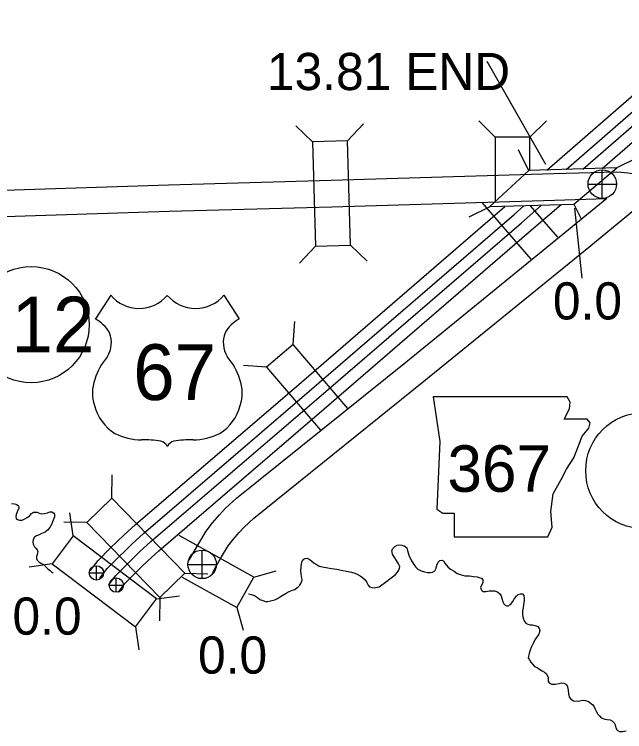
# Model space of a CAD drawing. Extents: x -939622 to -934222, y 1383701 to 1385301.
# Drawn here: x -936430.88 to -936410.08, y 1384424.88 to 1384449.32 of the extents above; entities that cross this region are included whole.
import ezdxf

# ---------------------------------------------------------------- set-up
doc = ezdxf.new("R2010")
doc.units = 0
for name, color, linetype in [('10', 7, 'Continuous'), ('15', 7, 'Continuous'), ('2', 7, 'Continuous'), ('20', 7, 'Continuous'), ('21', 7, 'Continuous'), ('22', 7, 'Continuous'), ('25', 7, 'Continuous'), ('26', 7, 'Continuous'), ('27', 7, 'Continuous')]:
    doc.layers.add(name, color=color, linetype=linetype)

msp = doc.modelspace()

# ---------------------------------------------------------------- linework, layer by layer
at = {"layer": '10'}
for points in [[(-936424.918, 1384430.721), (-936424.781, 1384430.966), (-936424.592, 1384431.291), (-936424.339, 1384431.72), (-936424.127, 1384431.995), (-936423.89, 1384432.276), (-936423.681, 1384432.493), (-936423.305, 1384432.841), (-936417.485, 1384437.522), (-936411.993, 1384441.99), (-936410.688, 1384443.056)], [(-936424.132, 1384430.282), (-936423.999, 1384430.52), (-936423.815, 1384430.836), (-936423.592, 1384431.215), (-936423.426, 1384431.43), (-936423.221, 1384431.673), (-936423.05, 1384431.851), (-936422.717, 1384432.159), (-936416.919, 1384436.823), (-936411.424, 1384441.292), (-936409.432, 1384442.92)]]:
    msp.add_lwpolyline(points, dxfattribs=at)
at = {"layer": '15'}
for points in [[(-936412.735, 1384444.016), (-936406.627, 1384449.323)], [(-936412.076, 1384444.042), (-936406.36, 1384449.008)], [(-936411.501, 1384444.045), (-936406.118, 1384448.722)], [(-936410.842, 1384444.071), (-936405.851, 1384448.408)], [(-936431.586, 1384443.322), (-936425.629, 1384443.512), (-936420.085, 1384443.668), (-936412.497, 1384443.896), (-936410.371, 1384443.959), (-936410.2, 1384443.942), (-936409.976, 1384443.925), (-936409.737, 1384443.884), (-936409.702, 1384443.877)], [(-936431.567, 1384442.422), (-936425.602, 1384442.613), (-936420.058, 1384442.769), (-936412.47, 1384442.997), (-936410.703, 1384443.048)], [(-936427.665, 1384429.89), (-936427.432, 1384430.198), (-936427.055, 1384430.572), (-936426.822, 1384430.803), (-936426.612, 1384431.007), (-936426.226, 1384431.357), (-936420.585, 1384436.197), (-936413.599, 1384442.222), (-936412.914, 1384442.817)], [(-936427.335, 1384429.641), (-936427.12, 1384429.926), (-936426.765, 1384430.279), (-936426.534, 1384430.508), (-936426.329, 1384430.706), (-936425.953, 1384431.047), (-936420.316, 1384435.885), (-936413.329, 1384441.91), (-936412.249, 1384442.849)], [(-936428.293, 1384430.364), (-936428.027, 1384430.717), (-936427.61, 1384431.131), (-936427.374, 1384431.365), (-936427.15, 1384431.582), (-936426.747, 1384431.947), (-936421.099, 1384436.794), (-936414.16, 1384442.778)], [(-936427.964, 1384430.115), (-936427.715, 1384430.445), (-936427.32, 1384430.838), (-936427.085, 1384431.071), (-936426.868, 1384431.281), (-936426.474, 1384431.638), (-936420.83, 1384436.482), (-936413.844, 1384442.505), (-936413.512, 1384442.794)]]:
    msp.add_lwpolyline(points, dxfattribs=at)
at = {"layer": '2'}
for points in [[(-936430.972, 1384432.656), (-936430.875, 1384432.644), (-936430.827, 1384432.63), (-936430.784, 1384432.607), (-936430.742, 1384432.575), (-936430.722, 1384432.531), (-936430.724, 1384432.491), (-936430.77, 1384432.403), (-936430.799, 1384432.342), (-936430.815, 1384432.285), (-936430.825, 1384432.2), (-936430.814, 1384432.143), (-936430.775, 1384432.108), (-936430.708, 1384432.089), (-936430.618, 1384432.094), (-936430.526, 1384432.13), (-936430.426, 1384432.187), (-936430.355, 1384432.249), (-936430.294, 1384432.322), (-936430.232, 1384432.357), (-936430.169, 1384432.365), (-936430.1, 1384432.361), (-936430.03, 1384432.329), (-936429.943, 1384432.308), (-936429.85, 1384432.319), (-936429.746, 1384432.34), (-936429.666, 1384432.369), (-936429.597, 1384432.371), (-936429.551, 1384432.339), (-936429.514, 1384432.289), (-936429.517, 1384432.199), (-936429.585, 1384432.034), (-936429.616, 1384431.946), (-936429.673, 1384431.839), (-936429.746, 1384431.747), (-936429.831, 1384431.679), (-936429.938, 1384431.631), (-936430.035, 1384431.586), (-936430.124, 1384431.551), (-936430.192, 1384431.51)], [(-936430.192, 1384431.51), (-936430.241, 1384431.436), (-936430.254, 1384431.349), (-936430.237, 1384431.268), (-936430.19, 1384431.185), (-936430.144, 1384431.135), (-936430.097, 1384431.076), (-936430.084, 1384431.013), (-936430.102, 1384430.92), (-936430.121, 1384430.847), (-936430.12, 1384430.784), (-936430.1, 1384430.727), (-936430.048, 1384430.674), (-936429.975, 1384430.622), (-936429.886, 1384430.576), (-936429.813, 1384430.512), (-936429.742, 1384430.433), (-936429.665, 1384430.369), (-936429.589, 1384430.31), (-936429.554, 1384430.301)], [(-936422.508, 1384429.391), (-936422.411, 1384429.348), (-936422.323, 1384429.321), (-936422.236, 1384429.323), (-936422.099, 1384429.351), (-936422.001, 1384429.38), (-936421.909, 1384429.422), (-936421.838, 1384429.469), (-936421.753, 1384429.528), (-936421.617, 1384429.607), (-936421.519, 1384429.664), (-936421.4, 1384429.7), (-936421.323, 1384429.732), (-936421.253, 1384429.788), (-936421.2, 1384429.829), (-936421.153, 1384429.878), (-936421.121, 1384429.927), (-936421.093, 1384429.985), (-936421.076, 1384430.049), (-936421.1, 1384430.249), (-936421.112, 1384430.375), (-936421.106, 1384430.505), (-936421.091, 1384430.599), (-936421.066, 1384430.69), (-936421.017, 1384430.76), (-936420.967, 1384430.788), (-936420.904, 1384430.79), (-936420.803, 1384430.739), (-936420.736, 1384430.692), (-936420.659, 1384430.628), (-936420.562, 1384430.571), (-936420.486, 1384430.527), (-936420.377, 1384430.497), (-936420.196, 1384430.463), (-936420.07, 1384430.442), (-936419.886, 1384430.417), (-936419.684, 1384430.38), (-936419.558, 1384430.353), (-936419.395, 1384430.316), (-936419.274, 1384430.28), (-936419.192, 1384430.252), (-936419.092, 1384430.191), (-936419.009, 1384430.139), (-936418.929, 1384430.057), (-936418.87, 1384429.963), (-936418.817, 1384429.871), (-936418.776, 1384429.818), (-936418.697, 1384429.79), (-936418.619, 1384429.786), (-936418.446, 1384429.823), (-936418.184, 1384430.014), (-936418.04, 1384430.123), (-936417.902, 1384430.232), (-936417.817, 1384430.318), (-936417.78, 1384430.382), (-936417.749, 1384430.459), (-936417.747, 1384430.516), (-936417.783, 1384430.599), (-936417.854, 1384430.711), (-936417.917, 1384430.806), (-936417.961, 1384430.874), (-936417.989, 1384430.936), (-936418.009, 1384430.996), (-936418.01, 1384431.059), (-936417.973, 1384431.135), (-936417.912, 1384431.191), (-936417.832, 1384431.232), (-936417.763, 1384431.249), (-936417.676, 1384431.24), (-936417.594, 1384431.212), (-936417.509, 1384431.142), (-936417.479, 1384431.058), (-936417.433, 1384430.894), (-936417.36, 1384430.725), (-936417.26, 1384430.574), (-936417.195, 1384430.485), (-936417.124, 1384430.421), (-936417.012, 1384430.367), (-936416.9, 1384430.328), (-936416.797, 1384430.306), (-936416.692, 1384430.303), (-936416.624, 1384430.32), (-936416.553, 1384430.367), (-936416.501, 1384430.455), (-936416.483, 1384430.552), (-936416.44, 1384430.653), (-936416.379, 1384430.711), (-936416.313, 1384430.731), (-936416.259, 1384430.706), (-936416.203, 1384430.626), (-936416.109, 1384430.496), (-936416.015, 1384430.423), (-936415.89, 1384430.348), (-936415.789, 1384430.276), (-936415.689, 1384430.236), (-936415.526, 1384430.198), (-936415.373, 1384430.188), (-936415.228, 1384430.173), (-936415.102, 1384430.153), (-936415.033, 1384430.139), (-936414.954, 1384430.111)], [(-936414.954, 1384430.111), (-936414.913, 1384430.055), (-936414.911, 1384429.965), (-936414.991, 1384429.798), (-936414.961, 1384429.708), (-936414.909, 1384429.664), (-936414.813, 1384429.655), (-936414.694, 1384429.685), (-936414.583, 1384429.685), (-936414.514, 1384429.678), (-936414.414, 1384429.653), (-936414.337, 1384429.583), (-936414.293, 1384429.506), (-936414.257, 1384429.384), (-936414.228, 1384429.306), (-936414.2, 1384429.244), (-936414.157, 1384429.194), (-936414.108, 1384429.165), (-936414.054, 1384429.167), (-936413.971, 1384429.214), (-936413.893, 1384429.315), (-936413.832, 1384429.419), (-936413.771, 1384429.499), (-936413.713, 1384429.552), (-936413.633, 1384429.581), (-936413.564, 1384429.583), (-936413.514, 1384429.518), (-936413.503, 1384429.431), (-936413.506, 1384429.337), (-936413.53, 1384429.216), (-936413.542, 1384429.108), (-936413.564, 1384428.996), (-936413.563, 1384428.87), (-936413.542, 1384428.747), (-936413.504, 1384428.655), (-936413.445, 1384428.581), (-936413.381, 1384428.541), (-936413.296, 1384428.522), (-936413.224, 1384428.518), (-936413.125, 1384428.502), (-936413.04, 1384428.471), (-936412.99, 1384428.397), (-936412.976, 1384428.317), (-936413.003, 1384428.202), (-936413.143, 1384428.017), (-936413.188, 1384427.908), (-936413.262, 1384427.756), (-936413.298, 1384427.658), (-936413.337, 1384427.546), (-936413.359, 1384427.455), (-936413.364, 1384427.398), (-936413.32, 1384427.327), (-936413.276, 1384427.256), (-936413.217, 1384427.188), (-936413.149, 1384427.103), (-936413.067, 1384427.066), (-936413, 1384427.025), (-936412.887, 1384426.959), (-936412.808, 1384426.913), (-936412.756, 1384426.866), (-936412.712, 1384426.789), (-936412.692, 1384426.724), (-936412.691, 1384426.655), (-936412.683, 1384426.595), (-936412.639, 1384426.533), (-936412.561, 1384426.499), (-936412.435, 1384426.502), (-936412.315, 1384426.523), (-936412.217, 1384426.544), (-936412.142, 1384426.54), (-936412.062, 1384426.485), (-936412.025, 1384426.41), (-936412.01, 1384426.303), (-936411.989, 1384426.177), (-936411.968, 1384426.069), (-936411.909, 1384425.986), (-936411.823, 1384425.934), (-936411.7, 1384425.923), (-936411.61, 1384425.937), (-936411.506, 1384425.952), (-936411.413, 1384425.942), (-936411.31, 1384425.906), (-936411.166, 1384425.792), (-936411.119, 1384425.731), (-936411.081, 1384425.653), (-936411.04, 1384425.564), (-936410.99, 1384425.478), (-936410.928, 1384425.411), (-936410.876, 1384425.358), (-936410.754, 1384425.304), (-936410.673, 1384425.303), (-936410.577, 1384425.291), (-936410.498, 1384425.245), (-936410.436, 1384425.183), (-936410.402, 1384425.112), (-936410.384, 1384425.019), (-936410.334, 1384424.933), (-936410.261, 1384424.884), (-936410.147, 1384424.887), (-936410.031, 1384424.917)], [(-936422.904, 1384429.578), (-936422.809, 1384429.56), (-936422.7, 1384429.518), (-936422.597, 1384429.449), (-936422.508, 1384429.391)]]:
    msp.add_lwpolyline(points, dxfattribs=at)
at = {"layer": '20'}
for p, q in [((-936420.715, 1384444.983), (-936421.291, 1384445.527)), ((-936419.528, 1384445.016), (-936418.984, 1384445.592)), ((-936414.495, 1384445.14), (-936415.055, 1384445.7)), ((-936413.307, 1384445.14), (-936412.747, 1384445.7)), ((-936413.307, 1384445.14), (-936414.495, 1384445.14)), ((-936414.495, 1384445.14), (-936414.495, 1384442.936)), ((-936413.307, 1384444.005), (-936413.307, 1384445.14)), ((-936413.344, 1384443.995), (-936413.7, 1384444.703)), ((-936410.352, 1384444.091), (-936409.644, 1384444.447)), ((-936410.349, 1384444.09), (-936413.344, 1384444)), ((-936411.816, 1384442.857), (-936410.349, 1384444.09)), ((-936414.676, 1384442.771), (-936413.344, 1384444)), ((-936414.948, 1384442.908), (-936413.282, 1384440.977)), ((-936414.676, 1384442.771), (-936411.816, 1384442.857)), ((-936412.361, 1384441.728), (-936413.288, 1384442.803)), ((-936411.816, 1384442.85), (-936411.567, 1384442.354)), ((-936414.679, 1384442.77), (-936415.387, 1384442.413)), ((-936420.615, 1384441.42), (-936421.159, 1384440.845)), ((-936419.428, 1384441.454), (-936418.852, 1384440.91)), ((-936421.383, 1384438.072), (-936421.323, 1384438.861)), ((-936421.383, 1384438.072), (-936422.285, 1384437.298)), ((-936419.511, 1384435.89), (-936421.383, 1384438.072)), ((-936422.285, 1384437.298), (-936423.075, 1384437.358)), ((-936422.285, 1384437.298), (-936420.442, 1384435.15)), ((-936427.554, 1384432.837), (-936427.542, 1384433.629)), ((-936428.879, 1384431.55), (-936428.989, 1384432.334)), ((-936428.407, 1384432.009), (-936429.199, 1384432.021)), ((-936422.714, 1384430.146), (-936425.261, 1384431.569)), ((-936429.595, 1384430.601), (-936430.379, 1384430.491)), ((-936422.714, 1384430.146), (-936421.952, 1384430.362)), ((-936425.158, 1384430.151), (-936423.293, 1384429.109)), ((-936425.073, 1384430.279), (-936424.281, 1384430.266)), ((-936423.293, 1384429.109), (-936422.714, 1384430.146)), ((-936426.034, 1384429.404), (-936425.249, 1384429.514)), ((-936425.926, 1384429.451), (-936425.938, 1384428.659)), ((-936423.293, 1384429.109), (-936423.078, 1384428.347)), ((-936426.749, 1384428.455), (-936426.639, 1384427.671))]:
    msp.add_line(p, q, dxfattribs=at)
for points in [[(-936420.715, 1384444.983), (-936420.615, 1384441.42), (-936419.428, 1384441.454), (-936419.528, 1384445.016)], [(-936428.407, 1384432.009), (-936425.926, 1384429.451), (-936425.073, 1384430.279), (-936427.554, 1384432.837)], [(-936426.034, 1384429.404), (-936428.879, 1384431.55), (-936429.595, 1384430.601), (-936426.749, 1384428.455)]]:
    msp.add_lwpolyline(points, close=True, dxfattribs=at)
at = {"layer": '21'}
msp.add_lwpolyline([(-936416.605, 1384436.291), (-936416.377, 1384434.769), (-936416.478, 1384432.46), (-936416.275, 1384432.333), (-936415.895, 1384432.333), (-936415.895, 1384431.521), (-936412.697, 1384431.521), (-936412.545, 1384431.85), (-936412.596, 1384432.383), (-936412.519, 1384432.992), (-936412.24, 1384433.475), (-936412.063, 1384433.83), (-936411.809, 1384434.211), (-936411.657, 1384434.617), (-936411.53, 1384434.946), (-936411.301, 1384435.226), (-936411.251, 1384435.403), (-936411.352, 1384435.53), (-936412.139, 1384435.53), (-936411.961, 1384435.885), (-936411.936, 1384436.114), (-936412.041, 1384436.289)], close=True, dxfattribs=at)
at = {"layer": '22'}
for p, q in [((-936427.597, 1384439.753), (-936428.116, 1384438.95)), ((-936423.736, 1384439.753), (-936423.217, 1384438.95))]:
    msp.add_line(p, q, dxfattribs=at)
for centre, radius, start, end in [((-936426.63, 1384440.567), 1.264, 220.075, 319.6701), ((-936424.703, 1384440.567), 1.264, 220.3299, 319.925), ((-936428.795, 1384437.784), 1.349, 30.7809, 59.9883), ((-936422.539, 1384437.784), 1.349, 120.0117, 149.2191), ((-936428.498, 1384438.14), 0.925, 328.8105, 21.2108), ((-936422.835, 1384438.14), 0.925, 158.7892, 211.1895), ((-936426.08, 1384436.244), 2.157, 138.9565, 162.6913), ((-936425.254, 1384436.244), 2.157, 17.3087, 41.0435), ((-936426.792, 1384436.421), 1.426, 160.9576, 197.3819), ((-936424.541, 1384436.421), 1.426, 342.6181, 19.0424), ((-936426.56, 1384436.425), 1.65, 195.1074, 237.1312), ((-936424.774, 1384436.425), 1.65, 302.8688, 344.8926), ((-936426.529, 1384436.945), 2.118, 244.0771, 269.5779), ((-936424.804, 1384436.945), 2.118, 270.4221, 295.9229), ((-936426.48, 1384430.947), 3.88, 81.1942, 90.9539), ((-936425.995, 1384434.426), 0.372, 28.0342, 72.9864), ((-936425.338, 1384434.426), 0.372, 107.0136, 151.9658), ((-936424.853, 1384430.947), 3.88, 89.0461, 98.8058)]:
    msp.add_arc(centre, radius, start, end, dxfattribs=at)
at = {"layer": '25'}
for p, q in [((-936414.778, 1384447.723), (-936412.775, 1384444.217)), ((-936411.523, 1384440.335), (-936411.773, 1384442.714))]:
    msp.add_line(p, q, dxfattribs=at)
at = {"layer": '26'}
for p, q in [((-936410.841, 1384443.053), (-936410.841, 1384444.028)), ((-936411.329, 1384443.54), (-936410.354, 1384443.54)), ((-936424.479, 1384430.096), (-936424.479, 1384431.071)), ((-936424.967, 1384430.584), (-936423.992, 1384430.584)), ((-936428.082, 1384430.05), (-936428.082, 1384430.538)), ((-936428.326, 1384430.294), (-936427.838, 1384430.294)), ((-936427.406, 1384429.631), (-936427.406, 1384430.119)), ((-936427.65, 1384429.875), (-936427.162, 1384429.875))]:
    msp.add_line(p, q, dxfattribs=at)
for centre, radius in [((-936410.841, 1384443.54), 0.487), ((-936424.479, 1384430.584), 0.487), ((-936428.082, 1384430.294), 0.244), ((-936427.406, 1384429.875), 0.244)]:
    msp.add_circle(centre, radius, dxfattribs=at)
at = {"layer": '27'}
for centre in [(-936430.307, 1384438.752), (-936409.427, 1384433.776)]:
    msp.add_circle(centre, 1.98, dxfattribs=at)

# ---------------------------------------------------------------- texts
at = {"layer": '21'}
msp.add_text('367', height=1.584, dxfattribs=at).set_placement((-936416.122, 1384433.055))
at = {"layer": '22'}
msp.add_text('67', height=1.9008, dxfattribs=at).set_placement((-936426.83, 1384436.182))
at = {"layer": '25'}
for s, p in [('13.81 END', (-936422.272, 1384446.742)), ('0.0', (-936412.525, 1384438.926)), ('0.0', (-936430.944, 1384428.188)), ('0.0', (-936424.62, 1384426.861))]:
    msp.add_text(s, height=1.2672, dxfattribs=at).set_placement(p)
at = {"layer": '27'}
msp.add_text('12', height=1.9008, dxfattribs=at).set_placement((-936430.98, 1384437.802))

doc.saveas('drawing.dxf')
